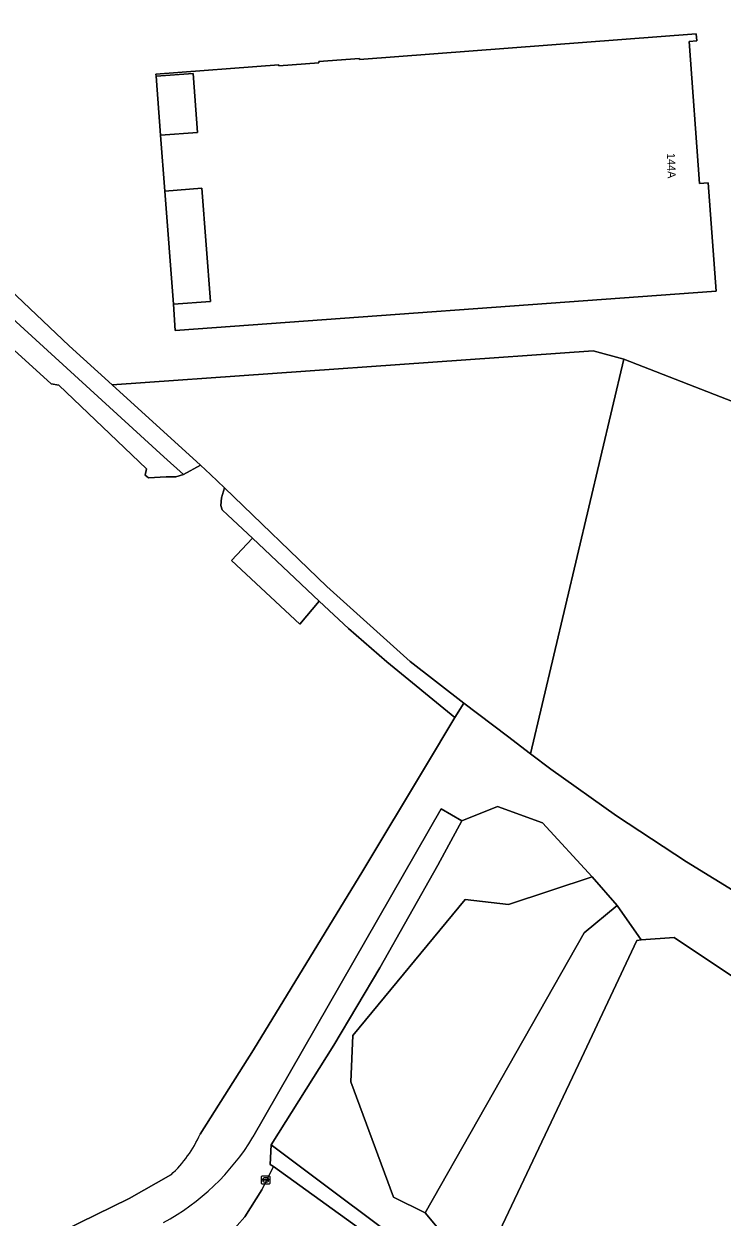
# Model space of a CAD drawing. Extents: x 160203 to 161530, y 379528 to 381797.
# Drawn here: x 160662.1 to 160748, y 380552.4 to 380699.1 of the extents above; entities that cross this region are included whole.
import ezdxf

# ---------------------------------------------------------------- set-up
doc = ezdxf.new("R2010")
doc.units = 0
for name, color, linetype in [('IMGEO_Erf', 7, 'Continuous'), ('IMGEO_Grasland_agrarisch', 7, 'Continuous'), ('IMGEO_Groenvoorziening', 7, 'Continuous'), ('IMGEO_Hek', 7, 'Continuous'), ('IMGEO_Houtwal', 7, 'Continuous'), ('IMGEO_Loofbos', 7, 'Continuous'), ('IMGEO_Pand', 7, 'Continuous'), ('IMGEO_Pand_nummerreeks', 7, 'Continuous'), ('IMGEO_Rioolput', 7, 'Continuous'), ('IMGEO_Terreindeel_onvherhard', 7, 'Continuous'), ('IMGEO_Voetpad_onverhard', 7, 'Continuous'), ('IMGEO_Waterloop', 7, 'Continuous')]:
    doc.layers.add(name, color=color, linetype=linetype)

msp = doc.modelspace()

# ---------------------------------------------------------------- linework, layer by layer
at = {"layer": 'IMGEO_Erf'}
msp.add_lwpolyline([(160653.08, 380673.31), (160667.68, 380659.51), (160672.96, 380654.7), (160732.12, 380658.89), (160735.88, 380657.84), (160759.66, 380648.6), (160773.61, 380643.68), (160785.98, 380639.57), (160793.62, 380637.24), (160800.02, 380635.88), (160807.89, 380634.51), (160811.08, 380660.23), (160811.37, 380663.36), (160811.54, 380664.41), (160811.46, 380665.26), (160810.64, 380667.26), (160805.64, 380667.42), (160798.02, 380667.66), (160798.41, 380680.23), (160796.76, 380680.28), (160797.24, 380695.79), (160806.52, 380695.49), (160811.52, 380695.34), (160811.63, 380699.29)], dxfattribs=at)
for points in [[(160744.79, 380697.86), (160744.86, 380696.99), (160743.92, 380696.92), (160745.2, 380679.45), (160746.24, 380679.53), (160747.21, 380666.23), (160680.72, 380661.37), (160680.48, 380664.6), (160679.42, 380678.51), (160678.9, 380685.39), (160678.35, 380692.64), (160678.33, 380692.9), (160693.44, 380694.04), (160693.45, 380693.92), (160698.39, 380694.29), (160698.37, 380694.45), (160703.36, 380694.82), (160703.36, 380694.71)], [(160683.47, 380685.74), (160682.92, 380692.99), (160678.35, 380692.64), (160678.9, 380685.39)], [(160679.42, 380678.51), (160680.48, 380664.6), (160685.04, 380664.95), (160683.99, 380678.86)]]:
    msp.add_lwpolyline(points, close=True, dxfattribs=at)
at = {"layer": 'IMGEO_Grasland_agrarisch'}
for points in [[(160686.77, 380642.05), (160685.06, 380643.7), (160683.83, 380644.81), (160681.71, 380643.69), (160680.77, 380643.4), (160679.6, 380643.4), (160677.41, 380643.27), (160677, 380643.61), (160677.2, 380644.36), (160666.38, 380654.67), (160665.46, 380654.82), (160653.65, 380665.52), (160640.16, 380677.59), (160630.09, 380686.48), (160622.14, 380693.79), (160592.64, 380681.2), (160558.49, 380665.9), (160509.85, 380645.18)], [(160683.77, 380562.6), (160690.34, 380572.96), (160703.8, 380594.98), (160711.49, 380607.8), (160715.09, 380613.82), (160706.75, 380620.67), (160702, 380624.75), (160698.43, 380628.11), (160696.02, 380625.29), (160687.64, 380633.11), (160690.21, 380635.85), (160687.18, 380638.7), (160686.48, 380639.34), (160686.33, 380639.87), (160686.4, 380640.8), (160686.77, 380642.05)], [(160657.08, 380367.01), (160675.12, 380384.28), (160690.5, 380399.79), (160703.76, 380412.84), (160702.84, 380413.86), (160743.68, 380453.92), (160786.3, 380496.09), (160779.54, 380500), (160766.96, 380507.35), (160758.18, 380512.48), (160743.15, 380522.32), (160692.79, 380558.61), (160691.35, 380555.76), (160689.27, 380552.45), (160688.32, 380551.37), (160687.17, 380550.3), (160685.91, 380549.35), (160684.56, 380548.54), (160683.13, 380547.88), (160681.64, 380547.37), (160675.38, 380544.83), (160669.06, 380542.46), (160654.23, 380535.66)], [(160660.89, 380547.76), (160675.05, 380554.68), (160680.19, 380557.61)]]:
    msp.add_lwpolyline(points, dxfattribs=at)
for points in [[(160735.88, 380657.84), (160732.12, 380658.89), (160672.96, 380654.7), (160683.83, 380644.81), (160685.06, 380643.7), (160686.77, 380642.05), (160699.35, 380629.93), (160709.62, 380620.7), (160716.19, 380615.59), (160721.58, 380611.5), (160724.41, 380609.36)], [(160806.33, 380619.41), (160807.89, 380634.51), (160800.02, 380635.88), (160793.62, 380637.24), (160785.98, 380639.57), (160773.61, 380643.68), (160759.66, 380648.6), (160735.88, 380657.84), (160724.41, 380609.36), (160726.91, 380607.47), (160734.98, 380601.72), (160743.6, 380596.08), (160750.38, 380591.88), (160752.72, 380590.44), (160764.75, 380583.64), (160772.85, 380578.66), (160776.31, 380576.15), (160790.19, 380567.67), (160793.64, 380565.36), (160801.24, 380562.92), (160802.87, 380583.32), (160803.41, 380589.08), (160804.86, 380605.07)], [(160785.05, 380500.37), (160788.37, 380529.85), (160786.23, 380546.87), (160784.74, 380557.01), (160783.06, 380559.39), (160780.2, 380561.18), (160756.3, 380577.25), (160749.85, 380581.56), (160742.05, 380586.77), (160738.01, 380586.47), (160737.46, 380586.42), (160730.68, 380571.93), (160717.98, 380545.13), (160744.66, 380526.72), (160784.79, 380499.12)]]:
    msp.add_lwpolyline(points, close=True, dxfattribs=at)
msp.add_arc((160669.66, 380568.95), 15.48, 312.8757, 335.7956, dxfattribs=at)
at = {"layer": 'IMGEO_Groenvoorziening'}
for points in [[(160623.04, 380694.18), (160622.14, 380693.79), (160630.09, 380686.48), (160640.16, 380677.59), (160653.65, 380665.52), (160665.46, 380654.82), (160666.38, 380654.67), (160677.2, 380644.36), (160677, 380643.61), (160677.41, 380643.27), (160679.6, 380643.4), (160680.77, 380643.4), (160681.71, 380643.69), (160679.32, 380645.87), (160659.26, 380664.16), (160632.89, 380689.2), (160626.22, 380695.53)], [(160731.01, 380587.36), (160735.04, 380590.71), (160731.98, 380594.23), (160721.71, 380590.84), (160716.37, 380591.43), (160702.54, 380574.72), (160702.29, 380569.03), (160707.55, 380554.87), (160711.45, 380552.92)], [(160738.01, 380586.47), (160737.7, 380586.89), (160735.04, 380590.71), (160731.01, 380587.36), (160711.45, 380552.92), (160717.98, 380545.13), (160730.68, 380571.93), (160737.46, 380586.42)]]:
    msp.add_lwpolyline(points, close=True, dxfattribs=at)
at = {"layer": 'IMGEO_Hek'}
for points in [[(160715.09, 380613.82), (160703.8, 380594.98), (160690.34, 380572.96), (160683.77, 380562.6)], [(160721.58, 380611.5), (160724.41, 380609.36), (160726.91, 380607.47), (160734.98, 380601.72), (160743.6, 380596.08), (160750.38, 380591.88), (160752.72, 380590.44), (160764.75, 380583.64), (160772.85, 380578.66), (160776.31, 380576.15), (160790.19, 380567.67), (160793.64, 380565.36), (160801.24, 380562.92)], [(160614.45, 380512.94), (160633.24, 380524.09), (160643.57, 380530.02), (160654.23, 380535.66), (160669.06, 380542.46), (160675.38, 380544.83), (160681.64, 380547.37), (160683.13, 380547.88), (160684.56, 380548.54), (160685.91, 380549.35), (160687.17, 380550.3), (160688.32, 380551.37), (160689.27, 380552.45), (160691.35, 380555.76), (160692.79, 380558.61)], [(160680.19, 380557.61), (160675.05, 380554.68), (160660.89, 380547.76), (160657.31, 380545.89)], [(160692.79, 380558.61), (160743.15, 380522.32), (160758.18, 380512.48), (160766.96, 380507.35)]]:
    msp.add_lwpolyline(points, dxfattribs=at)
msp.add_arc((160669.66, 380568.95), 15.48, 312.8757, 335.7956, dxfattribs=at)
at = {"layer": 'IMGEO_Houtwal'}
for points in [[(160672.96, 380654.7), (160667.68, 380659.51), (160653.08, 380673.31), (160633.59, 380692.1), (160629.71, 380695.79), (160628.81, 380696.65), (160627.87, 380697.54), (160627.53, 380697.86), (160621.5, 380699.73), (160592.72, 380687.25), (160558.46, 380672.68), (160504.94, 380650.02), (160505.42, 380647.48), (160506.92, 380644.83)], [(160509.85, 380645.18), (160558.49, 380665.9), (160592.64, 380681.2), (160622.14, 380693.79), (160623.04, 380694.18), (160626.22, 380695.53), (160632.89, 380689.2), (160659.26, 380664.16), (160679.32, 380645.87), (160681.71, 380643.69), (160683.83, 380644.81), (160672.96, 380654.7)]]:
    msp.add_lwpolyline(points, dxfattribs=at)
msp.add_lwpolyline([(160686.77, 380642.05), (160686.4, 380640.8), (160686.33, 380639.87), (160686.48, 380639.34), (160687.18, 380638.7), (160690.21, 380635.85), (160698.43, 380628.11), (160702, 380624.75), (160706.75, 380620.67), (160715.09, 380613.82), (160716.19, 380615.59), (160709.62, 380620.7), (160699.35, 380629.93)], close=True, dxfattribs=at)
at = {"layer": 'IMGEO_Loofbos'}
msp.add_lwpolyline([(160717.98, 380545.13), (160711.45, 380552.92), (160707.55, 380554.87), (160702.29, 380569.03), (160702.54, 380574.72), (160716.37, 380591.43), (160721.71, 380590.84), (160731.98, 380594.23), (160725.87, 380600.85), (160720.36, 380602.88), (160715.96, 380601.1), (160712.99, 380595.65), (160705.89, 380583.04), (160700.21, 380573.54), (160692.52, 380561.3), (160712.8, 380546.09)], dxfattribs=at)
msp.add_lwpolyline([(160767.7, 380508.38), (160736.58, 380528.85), (160712.8, 380546.09), (160692.52, 380561.3), (160692.37, 380558.88), (160692.79, 380558.61), (160743.15, 380522.32), (160758.18, 380512.48), (160766.96, 380507.35)], close=True, dxfattribs=at)
at = {"layer": 'IMGEO_Pand'}
msp.add_lwpolyline([(160678.35, 380692.64), (160682.92, 380692.99), (160683.47, 380685.74), (160678.9, 380685.39), (160679.42, 380678.51), (160683.99, 380678.86), (160685.04, 380664.95), (160680.48, 380664.6), (160680.72, 380661.37), (160747.21, 380666.23), (160746.24, 380679.53), (160745.2, 380679.45), (160743.92, 380696.92), (160744.86, 380696.99), (160744.79, 380697.86), (160703.36, 380694.71), (160703.36, 380694.82), (160698.37, 380694.45), (160698.39, 380694.29), (160693.45, 380693.92), (160693.44, 380694.04), (160678.33, 380692.9)], close=True, dxfattribs=at)
at = {"layer": 'IMGEO_Rioolput'}
for p, q in [((160691.34, 380556.54), (160691.34, 380557.4)), ((160691.41, 380557.47), (160692.26, 380557.47)), ((160692.34, 380557.4), (160692.34, 380556.54)), ((160692.26, 380556.47), (160691.41, 380556.47)), ((160691.59, 380556.96), (160691.59, 380556.98)), ((160692.03, 380556.93), (160691.63, 380556.93)), ((160691.64, 380557.01), (160692.03, 380557.01)), ((160691.82, 380557.25), (160691.85, 380557.25)), ((160691.85, 380556.69), (160691.82, 380556.69)), ((160692.08, 380556.98), (160692.08, 380556.96))]:
    msp.add_line(p, q, dxfattribs=at)
for points in [[(160691.34, 380556.54), (160691.34, 380557.4)], [(160691.41, 380557.47), (160692.26, 380557.47)], [(160692.34, 380557.4), (160692.34, 380556.54)], [(160692.26, 380556.47), (160691.41, 380556.47)]]:
    msp.add_lwpolyline(points, dxfattribs=at)
for centre, radius, start, end in [((160691.41, 380557.39), 0.0765, 91.552, 178.448), ((160691.41, 380557.39), 0.0765, 91.552, 178.448), ((160692.26, 380557.39), 0.0765, 1.552, 88.448), ((160692.26, 380557.39), 0.0765, 1.552, 88.448), ((160691.41, 380556.54), 0.0765, 181.552, 268.448), ((160691.41, 380556.54), 0.0765, 181.552, 268.448), ((160691.63, 380556.97), 0.0403, 85.8775, 175.7526), ((160691.63, 380556.96), 0.0366, 178.938, 274.7102), ((160692.04, 380556.97), 0.0386, 1.7309, 96.639), ((160692.04, 380556.97), 0.043, 264.8664, 352.4533), ((160692.26, 380556.54), 0.0765, 271.552, 358.448), ((160692.26, 380556.54), 0.0765, 271.552, 358.448)]:
    msp.add_arc(centre, radius, start, end, dxfattribs=at)
for centre, major_axis, ratio, start_param, end_param in [((160691.82, 380556.97), (-0.387, 0.002), 0.722429, 4.712389, 7.853982), ((160691.85, 380556.97), (-0.39, 0.002), 0.717154, 1.570796, 4.712389)]:
    msp.add_ellipse(centre, major_axis=major_axis, ratio=ratio, start_param=start_param, end_param=end_param, dxfattribs=at)
at = {"layer": 'IMGEO_Terreindeel_onvherhard'}
msp.add_lwpolyline([(160690.21, 380635.85), (160687.64, 380633.11), (160696.02, 380625.29), (160698.43, 380628.11)], close=True, dxfattribs=at)
at = {"layer": 'IMGEO_Voetpad_onverhard'}
for points in [[(160750.38, 380591.88), (160743.6, 380596.08), (160734.98, 380601.72), (160726.91, 380607.47), (160724.41, 380609.36), (160721.58, 380611.5), (160716.19, 380615.59), (160715.09, 380613.82), (160711.49, 380607.8), (160703.8, 380594.98), (160690.34, 380572.96), (160683.77, 380562.6)], [(160690.27, 380562.22), (160713.4, 380602.59), (160715.96, 380601.1), (160720.36, 380602.88), (160725.87, 380600.85), (160731.98, 380594.23), (160735.04, 380590.71), (160737.7, 380586.89), (160738.01, 380586.47), (160742.05, 380586.77), (160749.85, 380581.56)], [(160680.19, 380557.61), (160675.05, 380554.68), (160660.89, 380547.76)]]:
    msp.add_lwpolyline(points, dxfattribs=at)
for centre, radius, start, end in [((160665.41, 380577.26), 29.05, 298.4944, 328.83), ((160669.66, 380568.95), 15.48, 312.8757, 335.7956)]:
    msp.add_arc(centre, radius, start, end, dxfattribs=at)
at = {"layer": 'IMGEO_Waterloop'}
msp.add_lwpolyline([(160681.64, 380547.37), (160683.13, 380547.88), (160684.56, 380548.54), (160685.91, 380549.35), (160687.17, 380550.3), (160688.32, 380551.37), (160689.27, 380552.45), (160691.35, 380555.76), (160692.79, 380558.61), (160692.37, 380558.88), (160692.52, 380561.3), (160700.21, 380573.54), (160705.89, 380583.04), (160712.99, 380595.65), (160715.96, 380601.1), (160713.4, 380602.59), (160690.27, 380562.22)], dxfattribs=at)
msp.add_arc((160665.41, 380577.26), 29.05, 298.4944, 328.83, dxfattribs=at)

# ---------------------------------------------------------------- texts
at = {"layer": 'IMGEO_Pand_nummerreeks'}
msp.add_text('144A', height=1, rotation=272.1465, dxfattribs=at).set_placement((160741.16, 380683.19))

doc.saveas('drawing.dxf')
